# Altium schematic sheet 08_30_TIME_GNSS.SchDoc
size 289 x 396 mm
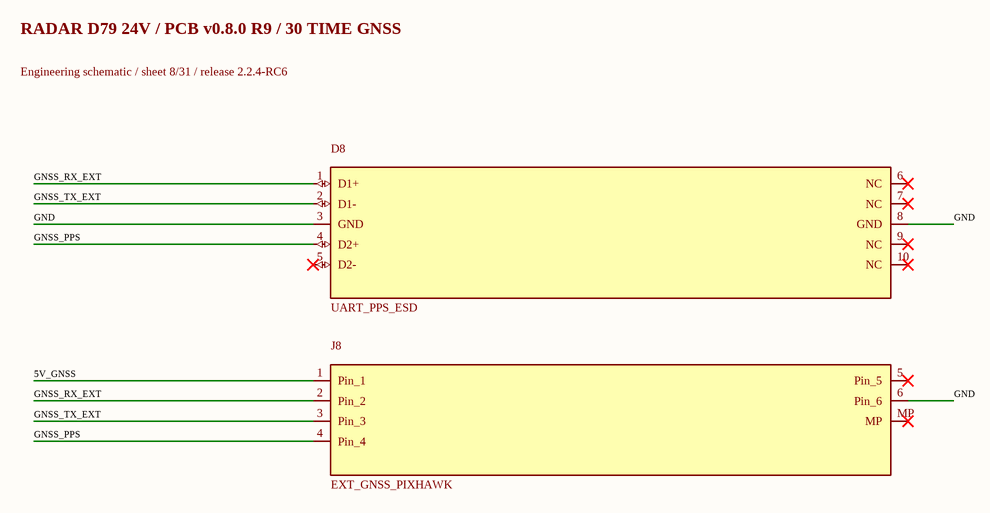
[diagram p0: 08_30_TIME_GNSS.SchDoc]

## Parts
D8  UART_PPS_ESD  [USON-10_2.5x1.0mm_P0.5mm]
J8  EXT_GNSS_PIXHAWK  [JST_GH_SM06B-GHS-TB_1x06-1MP_P1.25mm_Horizontal]

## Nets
5V_GNSS: J8.1(Pin_1)
GND: D8.3(GND) D8.8(GND) J8.6(Pin_6)
GNSS_PPS: D8.4(D2+) J8.4(Pin_4)
GNSS_RX_EXT: D8.1(D1+) J8.2(Pin_2)
GNSS_TX_EXT: D8.2(D1-) J8.3(Pin_3)

Not connected (* = marked no-connect by the designer): D8 5(D2-)* 6(NC)* 7(NC)* 9(NC)* 10(NC)*; J8 5(Pin_5)* MP*

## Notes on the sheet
- RADAR D79 24V / PCB v0.8.0 R9 / 30 TIME GNSS
- Engineering schematic / sheet 8/31 / release 2.2.4-RC6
